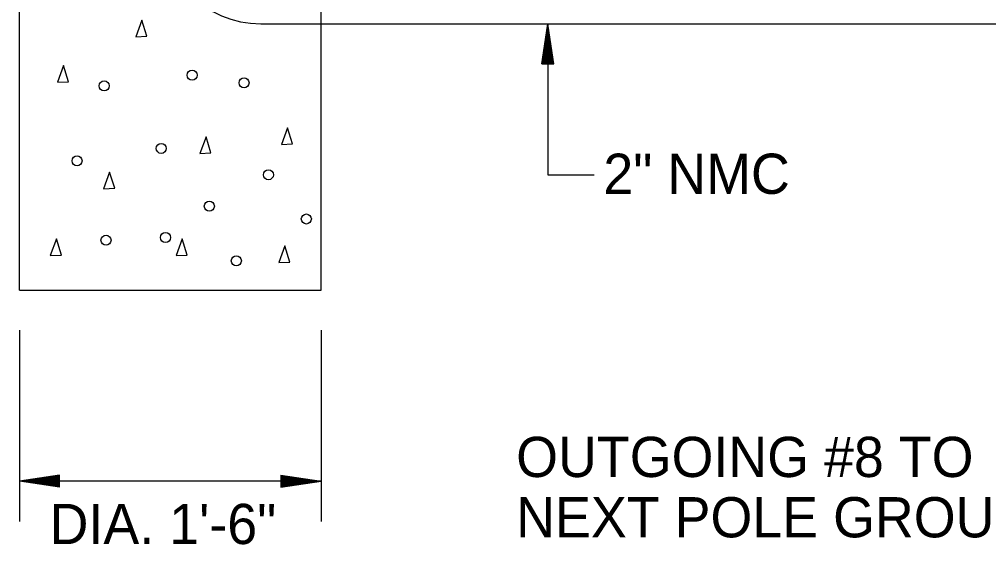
# Model space of a CAD drawing. Extents: x 1369885 to 1370886, y 379976 to 380616.
# Drawn here: x 1369997.1 to 1370105.6, y 380347.4 to 380406.2 of the extents above; entities that cross this region are included whole.
import ezdxf

# ---------------------------------------------------------------- set-up
doc = ezdxf.new("R2010")
doc.units = 0
doc.layers.add('R_Draft', color=7, linetype='Continuous')

msp = doc.modelspace()

# ---------------------------------------------------------------- linework, layer by layer
at = {"layer": 'R_Draft'}
for p, q in [((1369997.14, 380375.91), (1369997.14, 380443.41)), ((1370030.89, 380375.91), (1370030.89, 380443.41)), ((1370024.14, 380405.7), (1370135.45, 380405.7)), ((1370055.59, 380401.2), (1370056.26, 380405.7)), ((1370056.26, 380405.7), (1370056.26, 380388.79)), ((1370056.94, 380401.2), (1370056.26, 380405.7)), ((1370055.7, 380401.2), (1370056.26, 380404.95)), ((1370056.82, 380401.2), (1370056.26, 380404.95)), ((1370055.81, 380401.2), (1370056.26, 380404.18)), ((1370055.93, 380401.2), (1370056.26, 380403.43)), ((1370056.71, 380401.2), (1370056.26, 380404.18)), ((1370056.6, 380401.2), (1370056.26, 380403.43)), ((1370056.04, 380401.2), (1370056.26, 380402.66)), ((1370056.48, 380401.2), (1370056.26, 380402.66)), ((1370055.59, 380401.2), (1370056.94, 380401.2)), ((1370056.16, 380401.2), (1370056.26, 380401.91)), ((1370056.37, 380401.2), (1370056.26, 380401.91)), ((1370056.26, 380388.79), (1370061.45, 380388.79)), ((1369997.14, 380375.91), (1370030.89, 380375.91)), ((1369997.14, 380371.41), (1369997.14, 380350.03)), ((1370030.89, 380371.41), (1370030.89, 380350.03)), ((1370001.64, 380355.21), (1369997.14, 380354.53)), ((1370030.89, 380354.53), (1369997.14, 380354.53)), ((1370001.64, 380353.86), (1369997.14, 380354.53)), ((1370001.64, 380355.1), (1369997.89, 380354.53)), ((1370001.64, 380353.97), (1369997.89, 380354.53)), ((1370001.64, 380354.98), (1369998.67, 380354.53)), ((1370001.64, 380354.08), (1369998.67, 380354.53)), ((1370001.64, 380354.87), (1369999.42, 380354.53)), ((1370001.64, 380354.2), (1369999.42, 380354.53)), ((1370001.64, 380354.75), (1370000.18, 380354.53)), ((1370001.64, 380354.31), (1370000.18, 380354.53)), ((1370001.64, 380354.64), (1370000.93, 380354.53)), ((1370001.64, 380354.43), (1370000.93, 380354.53)), ((1370001.64, 380353.86), (1370001.64, 380355.21)), ((1370026.39, 380355.21), (1370030.89, 380354.53)), ((1370026.39, 380355.21), (1370026.39, 380353.86)), ((1370026.39, 380355.1), (1370030.14, 380354.53)), ((1370026.39, 380354.98), (1370029.37, 380354.53)), ((1370026.39, 380354.87), (1370028.62, 380354.53)), ((1370026.39, 380354.75), (1370027.85, 380354.53)), ((1370026.39, 380354.64), (1370027.1, 380354.53)), ((1370026.39, 380353.86), (1370030.89, 380354.53)), ((1370026.39, 380354.31), (1370027.85, 380354.53)), ((1370026.39, 380354.08), (1370029.37, 380354.53)), ((1370026.39, 380353.97), (1370030.14, 380354.53)), ((1370026.39, 380354.2), (1370028.62, 380354.53)), ((1370026.39, 380354.43), (1370027.1, 380354.53))]:
    msp.add_line(p, q, dxfattribs=at)
for points in [[(1370010.84, 380406.12), (1370010.16, 380404.25), (1370011.39, 380404.3), (1370010.84, 380406.12)], [(1370002.07, 380401.04), (1370001.39, 380399.17), (1370002.63, 380399.22), (1370002.07, 380401.04)], [(1370027.14, 380394.07), (1370026.46, 380392.2), (1370027.69, 380392.25), (1370027.14, 380394.07)], [(1370018.02, 380393.06), (1370017.33, 380391.2), (1370018.57, 380391.25), (1370018.02, 380393.06)], [(1370007.24, 380389.11), (1370006.56, 380387.24), (1370007.8, 380387.29), (1370007.24, 380389.11)], [(1370001.28, 380381.64), (1370000.6, 380379.77), (1370001.84, 380379.82), (1370001.28, 380381.64)], [(1370015.36, 380381.64), (1370014.68, 380379.77), (1370015.91, 380379.82), (1370015.36, 380381.64)], [(1370026.85, 380380.85), (1370026.17, 380378.98), (1370027.41, 380379.03), (1370026.85, 380380.85)]]:
    msp.add_lwpolyline(points, dxfattribs=at)
for centre in [(1370016.46, 380399.95), (1370006.62, 380398.75), (1370022.27, 380399.09), (1370013.01, 380391.76), (1370003.59, 380390.37), (1370025, 380388.81), (1370018.39, 380385.29), (1370029.24, 380383.86), (1370006.83, 380381.48), (1370013.48, 380381.79), (1370021.41, 380379.18)]:
    msp.add_circle(centre, 0.562, dxfattribs=at)
msp.add_arc((1370024.14, 380416.95), 11.25, 180, 270, dxfattribs=at)

# ---------------------------------------------------------------- texts
for s, p in [('2" NMC', (1370062.46, 380386.67)), ('OUTGOING #8 TO', (1370052.71, 380354.99)), ('NEXT POLE GROUND', (1370052.71, 380348.24)), ('DIA. 1\'-6"', (1370000.52, 380347.49))]:
    msp.add_text(s, height=4.5, dxfattribs=at).set_placement(p)

doc.saveas('drawing.dxf')
